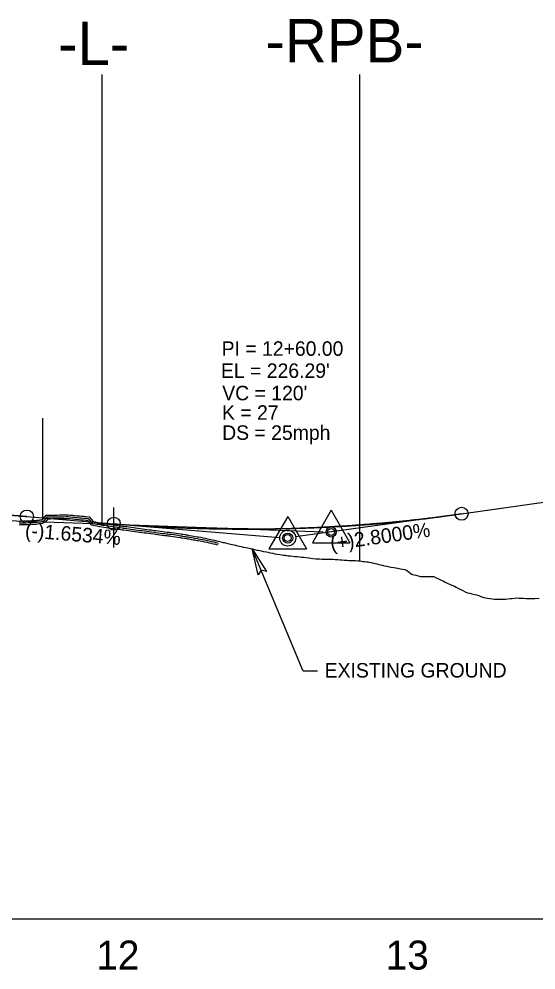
# Model space of a CAD drawing. Extents: x 2115752 to 2121174, y 562881 to 567245.
# Drawn here: x 2120289.6 to 2120468, y 564096.3 to 564424.5 of the extents above; entities that cross this region are included whole.
import ezdxf

# ---------------------------------------------------------------- set-up
doc = ezdxf.new("R2010")
doc.units = 0
for name, color, linetype in [('Exist Profile Cell', 7, 'Continuous'), ('Exist Vertical Profile Ground Line', 7, 'Continuous'), ('Exist Vertical Profile Horizontal Axis Label Major', 7, 'Continuous'), ('Prop PFL VPI Symbol CELL', 7, 'Continuous'), ('Prop Terminator CELL', 7, 'Continuous'), ('Prop Vertical Profile Curve Label', 7, 'Continuous'), ('Prop Vertical Profile Grade', 7, 'Continuous'), ('Prop Vertical Profile Grade Label', 7, 'Continuous'), ('Prop VPI Label', 7, 'Continuous'), ('Scratch_Level_1', 7, 'Continuous'), ('Scratch_Level_2', 7, 'Continuous')]:
    doc.layers.add(name, color=color, linetype=linetype)

msp = doc.modelspace()

# ---------------------------------------------------------------- linework, layer by layer
at = {"layer": 'Exist Profile Cell'}
msp.add_line((2120072.31, 564113.94), (2120643.55, 564113.94), dxfattribs=at)
at = {"layer": 'Exist Vertical Profile Ground Line'}
for points in [[(2120289.6, 564251.22), (2120290.07, 564251.24), (2120290.38, 564251.25), (2120291.15, 564251.27), (2120291.92, 564251.29), (2120292.87, 564251.32), (2120293.47, 564251.35), (2120294.25, 564251.39), (2120295.02, 564251.43), (2120295.38, 564251.45), (2120295.8, 564251.5), (2120296.57, 564251.59), (2120296.94, 564251.63), (2120297.34, 564251.68), (2120298.12, 564252.07), (2120298.98, 564253.3), (2120299.67, 564253.3), (2120300.44, 564253.3), (2120301.21, 564253.31), (2120301.99, 564253.32), (2120302.76, 564253.32), (2120303.64, 564253.33), (2120304.31, 564253.35), (2120305.09, 564253.36), (2120305.86, 564253.38), (2120306.63, 564253.37), (2120307.41, 564253.3), (2120308.18, 564253.23), (2120308.96, 564253.16), (2120309.73, 564253.09), (2120310.51, 564253.02), (2120311.28, 564252.96), (2120312.05, 564252.89), (2120312.83, 564252.83), (2120313.87, 564252.74), (2120314.5, 564251.83), (2120315.15, 564251.05), (2120315.47, 564250.99), (2120315.92, 564250.91), (2120316.7, 564250.77), (2120317.47, 564250.64), (2120318.64, 564250.43), (2120319.02, 564250.38), (2120319.79, 564250.28), (2120320.57, 564250.17), (2120321.34, 564250.07), (2120322.12, 564249.96), (2120322.54, 564249.9), (2120322.89, 564249.84), (2120323.66, 564249.73), (2120324.44, 564249.61), (2120325.29, 564249.49), (2120325.68, 564249.43), (2120325.98, 564249.4), (2120326.76, 564249.3), (2120327.56, 564249.2), (2120328.31, 564249.08), (2120329.08, 564248.96), (2120329.85, 564248.85), (2120330.63, 564248.75), (2120331.4, 564248.65), (2120332.17, 564248.55), (2120332.95, 564248.45), (2120333.72, 564248.36), (2120334.51, 564248.26), (2120335.27, 564248.16), (2120336.36, 564248), (2120336.82, 564247.93), (2120337.61, 564247.81), (2120338.36, 564247.69), (2120339.18, 564247.58), (2120339.91, 564247.51), (2120340.68, 564247.44), (2120341, 564247.42), (2120341.66, 564247.37), (2120342.23, 564247.29), (2120343.01, 564247.17), (2120343.78, 564247.06), (2120344.55, 564246.93), (2120345.4, 564246.79), (2120345.75, 564246.74), (2120346.1, 564246.68), (2120346.87, 564246.56), (2120347.19, 564246.51), (2120347.65, 564246.43), (2120348.02, 564246.36), (2120348.42, 564246.29), (2120349.19, 564246.15), (2120349.97, 564246.01), (2120350.38, 564245.94), (2120351.13, 564245.81), (2120351.52, 564245.75), (2120352.29, 564245.63), (2120353.06, 564245.5), (2120353.84, 564245.32), (2120354.76, 564245.13), (2120355.38, 564244.99), (2120356.32, 564244.78), (2120356.93, 564244.63), (2120357.7, 564244.44), (2120358.48, 564244.25)], [(2120358.48, 564244.25), (2120359.25, 564244.07), (2120360.03, 564243.89), (2120360.48, 564243.78), (2120360.8, 564243.71), (2120361.61, 564243.53), (2120362.58, 564243.31), (2120363.12, 564243.18), (2120363.89, 564243), (2120364.29, 564242.91), (2120364.67, 564242.82), (2120365.53, 564242.61), (2120366.22, 564242.46), (2120366.65, 564242.36), (2120366.99, 564242.28), (2120367.76, 564242.1), (2120368.54, 564241.94), (2120369.44, 564241.75), (2120370.08, 564241.61), (2120370.53, 564241.51), (2120370.86, 564241.43), (2120371.63, 564241.24), (2120372.03, 564241.14), (2120372.65, 564241.03), (2120373.18, 564240.92), (2120373.95, 564240.77), (2120374.95, 564240.58), (2120375.5, 564240.45), (2120376.27, 564240.28), (2120377.15, 564240.1), (2120377.82, 564239.97), (2120378.59, 564239.83), (2120379.59, 564239.66), (2120380.14, 564239.58), (2120380.91, 564239.47), (2120381.37, 564239.41), (2120381.69, 564239.36), (2120382.02, 564239.32), (2120382.46, 564239.26), (2120383.24, 564239.18), (2120384.78, 564239.02), (2120385.56, 564238.95), (2120386.33, 564238.88), (2120387.1, 564238.81), (2120387.88, 564238.72), (2120388.65, 564238.63), (2120389.73, 564238.52), (2120390.2, 564238.46), (2120390.97, 564238.36), (2120391.97, 564238.25), (2120392.52, 564238.21), (2120393.29, 564238.16), (2120394.11, 564238.12), (2120394.53, 564238.12), (2120395.07, 564238.08), (2120395.61, 564238.08), (2120396.39, 564238.08), (2120397.16, 564238.08), (2120397.94, 564238.04), (2120398.71, 564238.01), (2120399.6, 564237.92), (2120400.26, 564237.88), (2120400.65, 564237.86), (2120401.03, 564237.83), (2120401.8, 564237.77), (2120402.16, 564237.74), (2120402.75, 564237.69), (2120403.35, 564237.67), (2120404.12, 564237.64), (2120404.9, 564237.61), (2120405.32, 564237.6), (2120405.67, 564237.58), (2120406.45, 564237.54), (2120407.33, 564237.5), (2120408.25, 564237.32), (2120408.77, 564237.27), (2120409.54, 564237.19), (2120409.96, 564237.15), (2120410.31, 564237.07), (2120411.09, 564236.89), (2120411.86, 564236.72), (2120412.63, 564236.55), (2120413.06, 564236.45), (2120413.4, 564236.37), (2120414.18, 564236.18), (2120414.95, 564235.99), (2120415.3, 564235.91), (2120415.72, 564235.82), (2120416.5, 564235.65), (2120417.27, 564235.49), (2120418.04, 564235.31), (2120418.88, 564235.17), (2120419.59, 564235.06), (2120420.03, 564235), (2120420.36, 564234.94), (2120420.8, 564234.87), (2120421.19, 564234.76), (2120421.91, 564234.64), (2120422.7, 564234.5), (2120423.46, 564234.21), (2120424.23, 564233.56)], [(2120424.23, 564233.56), (2120425, 564232.93), (2120425.78, 564232.72), (2120426.55, 564232.51), (2120427.32, 564232.3), (2120428.13, 564232.08), (2120428.87, 564232.07), (2120429.64, 564232.07), (2120430.41, 564232.06), (2120431.19, 564232.06), (2120431.96, 564232.07), (2120432.74, 564232.07), (2120433.51, 564231.69), (2120434.28, 564231.3), (2120435.05, 564230.92), (2120436.04, 564230.44), (2120436.6, 564230.18), (2120437.37, 564229.83), (2120438.15, 564229.49), (2120438.92, 564229.14), (2120439.85, 564228.73), (2120440.46, 564228.41), (2120441.24, 564228.01), (2120442.01, 564227.61), (2120442.78, 564227.22), (2120443.56, 564226.82), (2120444.33, 564226.5), (2120445.1, 564226.33), (2120445.88, 564226.16), (2120446.92, 564225.94), (2120447.42, 564225.76), (2120448.2, 564225.49), (2120448.97, 564225.23), (2120450.01, 564224.88), (2120450.52, 564224.79), (2120451.29, 564224.66), (2120452.06, 564224.54), (2120452.84, 564224.41), (2120453.61, 564224.3), (2120454.02, 564224.23), (2120454.38, 564224.24), (2120455.15, 564224.25), (2120455.93, 564224.27), (2120456.7, 564224.29), (2120457.15, 564224.31), (2120457.47, 564224.33), (2120458.25, 564224.4), (2120459.02, 564224.47), (2120459.79, 564224.54), (2120460.57, 564224.62), (2120461.34, 564224.68), (2120462.11, 564224.64), (2120462.89, 564224.61), (2120463.66, 564224.58), (2120464.43, 564224.56), (2120465.21, 564224.54), (2120465.98, 564224.53), (2120466.75, 564224.52), (2120467.52, 564224.51), (2120469.07, 564224.58)]]:
    msp.add_lwpolyline(points, dxfattribs=at)
at = {"layer": 'Prop PFL VPI Symbol CELL'}
for p, q in [((2120382.3, 564252.84), (2120375.85, 564241.64)), ((2120382.3, 564252.84), (2120388.8, 564241.64)), ((2120375.85, 564241.64), (2120388.8, 564241.64))]:
    msp.add_line(p, q, dxfattribs=at)
for radius in [1.75, 1.2]:
    msp.add_circle((2120382.31, 564245.36), radius, dxfattribs=at)
at = {"layer": 'Prop Terminator CELL'}
msp.add_lwpolyline([(2120372.11, 564232.7), (2120370.08, 564241.61), (2120375.04, 564233.87), (2120373.12, 564234.31)], close=True, dxfattribs=at)
at = {"layer": 'Prop Vertical Profile Curve Label'}
for centre in [(2120292.31, 564252.8), (2120442.31, 564253.76), (2120322.31, 564250.32)]:
    msp.add_circle(centre, 2.25, dxfattribs=at)
at = {"layer": 'Prop Vertical Profile Grade'}
for p, q in [((2120442.31, 564253.76), (2120553.55, 564269.34)), ((2120292.31, 564252.8), (2120322.31, 564250.32))]:
    msp.add_line(p, q, dxfattribs=at)
for points in [[(2120192.31, 564264.44), (2120194.31, 564264.14), (2120196.31, 564263.84), (2120198.31, 564263.55), (2120200.31, 564263.26), (2120202.31, 564262.97), (2120204.31, 564262.68), (2120206.31, 564262.4), (2120208.31, 564262.12), (2120210.31, 564261.85), (2120212.31, 564261.57), (2120214.31, 564261.3), (2120216.31, 564261.03), (2120218.31, 564260.76), (2120220.31, 564260.5), (2120222.31, 564260.24), (2120224.31, 564259.98), (2120226.31, 564259.73), (2120228.31, 564259.47), (2120230.31, 564259.22), (2120232.31, 564258.97), (2120234.31, 564258.73), (2120236.31, 564258.49), (2120238.31, 564258.25), (2120240.31, 564258.01), (2120242.31, 564257.78), (2120244.31, 564257.55), (2120246.31, 564257.32), (2120248.31, 564257.09), (2120250.31, 564256.87), (2120252.31, 564256.65), (2120254.31, 564256.43), (2120256.31, 564256.22), (2120258.31, 564256), (2120260.31, 564255.79), (2120262.31, 564255.59), (2120264.31, 564255.38), (2120266.31, 564255.18), (2120268.31, 564254.98), (2120270.31, 564254.78), (2120272.31, 564254.59), (2120274.31, 564254.4), (2120276.31, 564254.21), (2120278.31, 564254.03), (2120280.31, 564253.84), (2120282.31, 564253.66), (2120284.31, 564253.49), (2120286.31, 564253.31), (2120288.31, 564253.14), (2120290.31, 564252.97), (2120292.31, 564252.8)], [(2120322.31, 564250.32), (2120324.71, 564250.13), (2120327.11, 564249.95), (2120329.51, 564249.78), (2120331.91, 564249.61), (2120334.31, 564249.46), (2120336.71, 564249.32), (2120339.11, 564249.2), (2120341.51, 564249.08), (2120343.91, 564248.97), (2120346.31, 564248.87), (2120348.71, 564248.79), (2120351.11, 564248.71), (2120353.51, 564248.65), (2120355.91, 564248.59), (2120358.31, 564248.55), (2120360.71, 564248.52), (2120363.11, 564248.49), (2120365.51, 564248.48), (2120367.91, 564248.48), (2120370.31, 564248.49), (2120372.71, 564248.51), (2120375.11, 564248.54), (2120377.51, 564248.59), (2120379.91, 564248.64), (2120382.31, 564248.7), (2120384.71, 564248.78), (2120387.11, 564248.86), (2120389.51, 564248.96), (2120391.91, 564249.06), (2120394.31, 564249.18), (2120396.71, 564249.31), (2120399.11, 564249.45), (2120401.51, 564249.59), (2120403.91, 564249.75), (2120406.31, 564249.92), (2120408.71, 564250.11), (2120411.11, 564250.3), (2120413.51, 564250.5), (2120415.91, 564250.71), (2120418.31, 564250.94), (2120420.71, 564251.17), (2120423.11, 564251.42), (2120425.51, 564251.67), (2120427.91, 564251.94), (2120430.31, 564252.22), (2120432.71, 564252.5), (2120435.11, 564252.8), (2120437.51, 564253.11), (2120439.91, 564253.43), (2120442.31, 564253.76)]]:
    msp.add_spline(points, degree=3, dxfattribs=at)
at = {"layer": 'Prop VPI Label'}
for p, q in [((2120292.31, 564252.8), (2120245.05, 564256.71)), ((2120442.31, 564253.76), (2120385.03, 564245.74)), ((2120322.31, 564250.32), (2120379.57, 564245.59))]:
    msp.add_line(p, q, dxfattribs=at)
msp.add_lwpolyline([(2120392.62, 564199.47), (2120387.64, 564199.47), (2120370.08, 564241.61)], dxfattribs=at)
msp.add_circle((2120382.31, 564245.36), 2.75, dxfattribs=at)
at = {"layer": 'Scratch_Level_1'}
for p, q in [((2120318.25, 564250.49), (2120318.25, 564405.33)), ((2120407.22, 564250.17), (2120407.22, 564405.33)), ((2120297.88, 564251.95), (2120297.88, 564286.72)), ((2120322.31, 564242.08), (2120322.31, 564255.96)), ((2120407.22, 564237.51), (2120407.22, 564250.17))]:
    msp.add_line(p, q, dxfattribs=at)
for points in [[(2120289.62, 564250.6), (2120290.09, 564250.61), (2120290.39, 564250.62), (2120291.17, 564250.64), (2120291.94, 564250.67), (2120292.9, 564250.7), (2120293.5, 564250.73), (2120294.28, 564250.77), (2120295.06, 564250.81), (2120295.43, 564250.83), (2120295.87, 564250.88), (2120296.64, 564250.97), (2120297.02, 564251.01), (2120297.53, 564251.07), (2120298.54, 564251.58), (2120299.31, 564252.67), (2120299.67, 564252.67), (2120300.44, 564252.68), (2120301.22, 564252.69), (2120301.99, 564252.69), (2120302.77, 564252.7), (2120303.65, 564252.71), (2120304.32, 564252.72), (2120305.1, 564252.74), (2120305.87, 564252.75), (2120306.6, 564252.75), (2120307.35, 564252.68), (2120308.13, 564252.61), (2120308.9, 564252.54), (2120309.68, 564252.47), (2120310.45, 564252.4), (2120311.23, 564252.33), (2120312, 564252.27), (2120312.78, 564252.2), (2120313.52, 564252.14), (2120314, 564251.45), (2120314.82, 564250.48), (2120315.36, 564250.38), (2120315.81, 564250.3), (2120316.59, 564250.16), (2120317.36, 564250.02), (2120318.54, 564249.82), (2120318.94, 564249.76), (2120319.71, 564249.66), (2120320.48, 564249.55), (2120321.26, 564249.45), (2120322.03, 564249.34), (2120322.45, 564249.28), (2120322.8, 564249.23), (2120323.57, 564249.11), (2120324.35, 564249), (2120325.2, 564248.87), (2120325.6, 564248.81), (2120325.91, 564248.78), (2120326.68, 564248.68), (2120327.47, 564248.58), (2120328.21, 564248.46), (2120328.99, 564248.34), (2120329.77, 564248.23), (2120330.55, 564248.13), (2120331.32, 564248.03), (2120332.09, 564247.93), (2120332.87, 564247.83), (2120333.65, 564247.74), (2120334.43, 564247.64), (2120335.18, 564247.54), (2120336.27, 564247.38), (2120336.72, 564247.31), (2120337.52, 564247.19), (2120338.27, 564247.07), (2120339.11, 564246.95), (2120339.86, 564246.89), (2120340.63, 564246.82), (2120340.96, 564246.79), (2120341.59, 564246.75), (2120342.14, 564246.67), (2120342.91, 564246.55), (2120343.68, 564246.44), (2120344.45, 564246.31), (2120345.3, 564246.18), (2120345.65, 564246.12), (2120346, 564246.06), (2120346.78, 564245.94), (2120347.09, 564245.9), (2120347.53, 564245.81), (2120347.91, 564245.74), (2120348.31, 564245.67), (2120349.08, 564245.53), (2120349.86, 564245.39), (2120350.28, 564245.32), (2120351.03, 564245.2), (2120351.42, 564245.14), (2120352.19, 564245.02), (2120352.94, 564244.88), (2120353.7, 564244.71), (2120354.62, 564244.52), (2120355.25, 564244.38), (2120356.18, 564244.17), (2120356.78, 564244.02), (2120357.56, 564243.83), (2120358.33, 564243.65)], [(2120289.65, 564249.97), (2120290.11, 564249.99), (2120290.41, 564250), (2120291.19, 564250.02), (2120291.96, 564250.04), (2120292.92, 564250.07), (2120293.54, 564250.1), (2120294.31, 564250.14), (2120295.09, 564250.18), (2120295.48, 564250.21), (2120295.94, 564250.26), (2120296.71, 564250.35), (2120297.09, 564250.39), (2120297.71, 564250.46), (2120298.96, 564251.1), (2120299.63, 564252.05), (2120299.67, 564252.05), (2120300.45, 564252.05), (2120301.22, 564252.06), (2120302, 564252.07), (2120302.78, 564252.07), (2120303.66, 564252.08), (2120304.33, 564252.1), (2120305.11, 564252.11), (2120305.87, 564252.13), (2120306.57, 564252.12), (2120307.29, 564252.06), (2120308.07, 564251.99), (2120308.84, 564251.91), (2120309.62, 564251.84), (2120310.4, 564251.78), (2120311.17, 564251.71), (2120311.95, 564251.65), (2120312.73, 564251.58), (2120313.17, 564251.54), (2120313.5, 564251.07), (2120314.48, 564249.91), (2120315.25, 564249.76), (2120315.7, 564249.68), (2120316.48, 564249.54), (2120317.26, 564249.41), (2120318.45, 564249.2), (2120318.85, 564249.14), (2120319.63, 564249.04), (2120320.4, 564248.93), (2120321.17, 564248.83), (2120321.94, 564248.72), (2120322.36, 564248.66), (2120322.7, 564248.61), (2120323.48, 564248.49), (2120324.25, 564248.38), (2120325.11, 564248.25), (2120325.51, 564248.19), (2120325.83, 564248.15), (2120326.6, 564248.06), (2120327.38, 564247.96), (2120328.11, 564247.84), (2120328.9, 564247.72), (2120329.68, 564247.61), (2120330.46, 564247.51), (2120331.24, 564247.41), (2120332.02, 564247.31), (2120332.8, 564247.21), (2120333.57, 564247.12), (2120334.35, 564247.02), (2120335.09, 564246.92), (2120336.18, 564246.77), (2120336.62, 564246.7), (2120337.42, 564246.57), (2120338.18, 564246.46), (2120339.04, 564246.33), (2120339.8, 564246.27), (2120340.58, 564246.2), (2120340.91, 564246.17), (2120341.52, 564246.13), (2120342.05, 564246.05), (2120342.82, 564245.94), (2120343.58, 564245.82), (2120344.35, 564245.69), (2120345.2, 564245.56), (2120345.55, 564245.5), (2120345.91, 564245.45), (2120346.68, 564245.33), (2120346.98, 564245.28), (2120347.42, 564245.2), (2120347.8, 564245.13), (2120348.2, 564245.06), (2120348.97, 564244.92), (2120349.75, 564244.78), (2120350.17, 564244.7), (2120350.93, 564244.58), (2120351.32, 564244.52), (2120352.08, 564244.4), (2120352.81, 564244.27), (2120353.57, 564244.1), (2120354.49, 564243.91), (2120355.11, 564243.77), (2120356.04, 564243.57), (2120356.63, 564243.42), (2120357.41, 564243.23), (2120358.19, 564243.04)]]:
    msp.add_lwpolyline(points, dxfattribs=at)
at = {"layer": 'Scratch_Level_2'}
for p, q in [((2120437.31, 564253.06), (2120553.55, 564269.34)), ((2120397.3, 564254.94), (2120390.85, 564243.74)), ((2120397.3, 564254.94), (2120403.8, 564243.74)), ((2120248.31, 564252.68), (2120357.31, 564248.86)), ((2120437.31, 564253.06), (2120400.03, 564247.84)), ((2120357.31, 564248.86), (2120394.56, 564247.56)), ((2120390.85, 564243.74), (2120403.8, 564243.74))]:
    msp.add_line(p, q, dxfattribs=at)
for radius in [1.75, 1.2]:
    msp.add_circle((2120397.31, 564247.46), radius, dxfattribs=at)
msp.add_spline([(2120357.31, 564248.86), (2120358.91, 564248.81), (2120360.51, 564248.76), (2120362.11, 564248.72), (2120363.71, 564248.68), (2120365.31, 564248.65), (2120366.91, 564248.63), (2120368.51, 564248.61), (2120370.11, 564248.59), (2120371.71, 564248.59), (2120373.31, 564248.58), (2120374.91, 564248.59), (2120376.51, 564248.59), (2120378.11, 564248.61), (2120379.71, 564248.63), (2120381.31, 564248.65), (2120382.91, 564248.68), (2120384.51, 564248.72), (2120386.11, 564248.76), (2120387.71, 564248.81), (2120389.31, 564248.86), (2120390.91, 564248.92), (2120392.51, 564248.99), (2120394.11, 564249.06), (2120395.71, 564249.13), (2120397.31, 564249.21), (2120398.91, 564249.3), (2120400.51, 564249.39), (2120402.11, 564249.49), (2120403.71, 564249.59), (2120405.31, 564249.7), (2120406.91, 564249.82), (2120408.51, 564249.94), (2120410.11, 564250.06), (2120411.71, 564250.2), (2120413.31, 564250.33), (2120414.91, 564250.48), (2120416.51, 564250.62), (2120418.11, 564250.78), (2120419.71, 564250.94), (2120421.31, 564251.1), (2120422.91, 564251.27), (2120424.51, 564251.45), (2120426.11, 564251.63), (2120427.71, 564251.82), (2120429.31, 564252.01), (2120430.91, 564252.21), (2120432.51, 564252.42), (2120434.11, 564252.63), (2120435.71, 564252.84), (2120437.31, 564253.06)], degree=3, dxfattribs=at)

# ---------------------------------------------------------------- texts
at = {"layer": 'Exist Vertical Profile Horizontal Axis Label Major'}
for s, p in [('12', (2120316.28, 564096.44)), ('13', (2120416.11, 564096.44))]:
    msp.add_text(s, height=10, dxfattribs=at).set_placement(p)
at = {"layer": 'Prop Vertical Profile Curve Label'}
for s, p in [("VC = 120'", (2120359.73, 564292.91)), ('K = 27', (2120359.65, 564286.19)), ('DS = 25mph', (2120359.7, 564279.26))]:
    msp.add_text(s, height=5, dxfattribs=at).set_placement(p)
at = {"layer": 'Prop Vertical Profile Grade Label'}
for s, rotation, p in [('(-)1.6534%', 355.274, (2120291.55, 564245.65)), ('(+)2.8000%', 7.9697, (2120397.32, 564241.06))]:
    msp.add_text(s, height=5, rotation=rotation, dxfattribs=at).set_placement(p)
at = {"layer": 'Prop VPI Label'}
for s, p in [('PI = 12+60.00', (2120359.51, 564308.27)), ("EL = 226.29'", (2120359.29, 564300.64)), ('EXISTING GROUND', (2120395.06, 564197.23))]:
    msp.add_text(s, height=5, dxfattribs=at).set_placement(p)
at = {"layer": 'Scratch_Level_1'}
for s, p in [('-L-', (2120303.12, 564408.64)), ('-RPB-', (2120374.64, 564409.51))]:
    msp.add_text(s, height=15, dxfattribs=at).set_placement(p)

doc.saveas('drawing.dxf')
